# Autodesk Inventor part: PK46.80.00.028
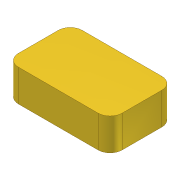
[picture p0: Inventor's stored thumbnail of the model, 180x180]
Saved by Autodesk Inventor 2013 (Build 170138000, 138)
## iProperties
Created: 2005-05
Part Number: PK46.80.00.028
Material: Steel, Mild
Document SubType Name: Modeling
Designer: salex
Manufacturer: Standard
Standards Organization: Custom
Density: 7.86 g/cm^3
Mass: 3209.04 g
Surface Area: 361.836 cm^2
Volume: 408.275 cm^3
Author: salex
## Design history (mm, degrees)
sketch "Эскиз1"
  geometry: L1 (0, 0)-(130, 0); L2 (130, 0)-(130, 80); L3 (130, 80)-(0, 80); L4 (0, 80)-(0, 0)
  constraints: 8 end point, 2 parallel, 1 horizontal, 1 perpendicular, 1 other
  dimensions: "d0" = 80 distance of L3.end L1.start; "d1" = 130 distance of L1.start L1.end
extrude "Выдавливание1" new body sketch "Эскиз1" distance "d2" = 40; taper "d3" = 0 deg
fillet "Сопряжение1" dims "d4" = 15
body "Solid1"
